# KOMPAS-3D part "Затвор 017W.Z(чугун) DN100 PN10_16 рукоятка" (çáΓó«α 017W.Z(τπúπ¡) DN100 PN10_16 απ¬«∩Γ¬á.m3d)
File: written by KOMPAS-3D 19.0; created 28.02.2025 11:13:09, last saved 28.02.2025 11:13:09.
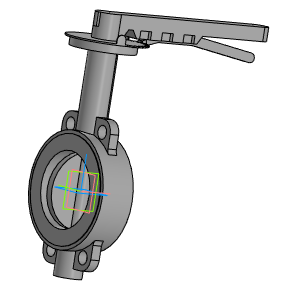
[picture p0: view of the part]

Document properties: Автор: Евгений; Полное имя файла: Затвор 017W.Z(чугун) DN100 PN10_16 рукоятка.a3d

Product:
- Part/product: Затвор 017W.Z(чугун) DN100 PN10_16 рукоятка
    Масса: 15.9458

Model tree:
1. Операция без истории:1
